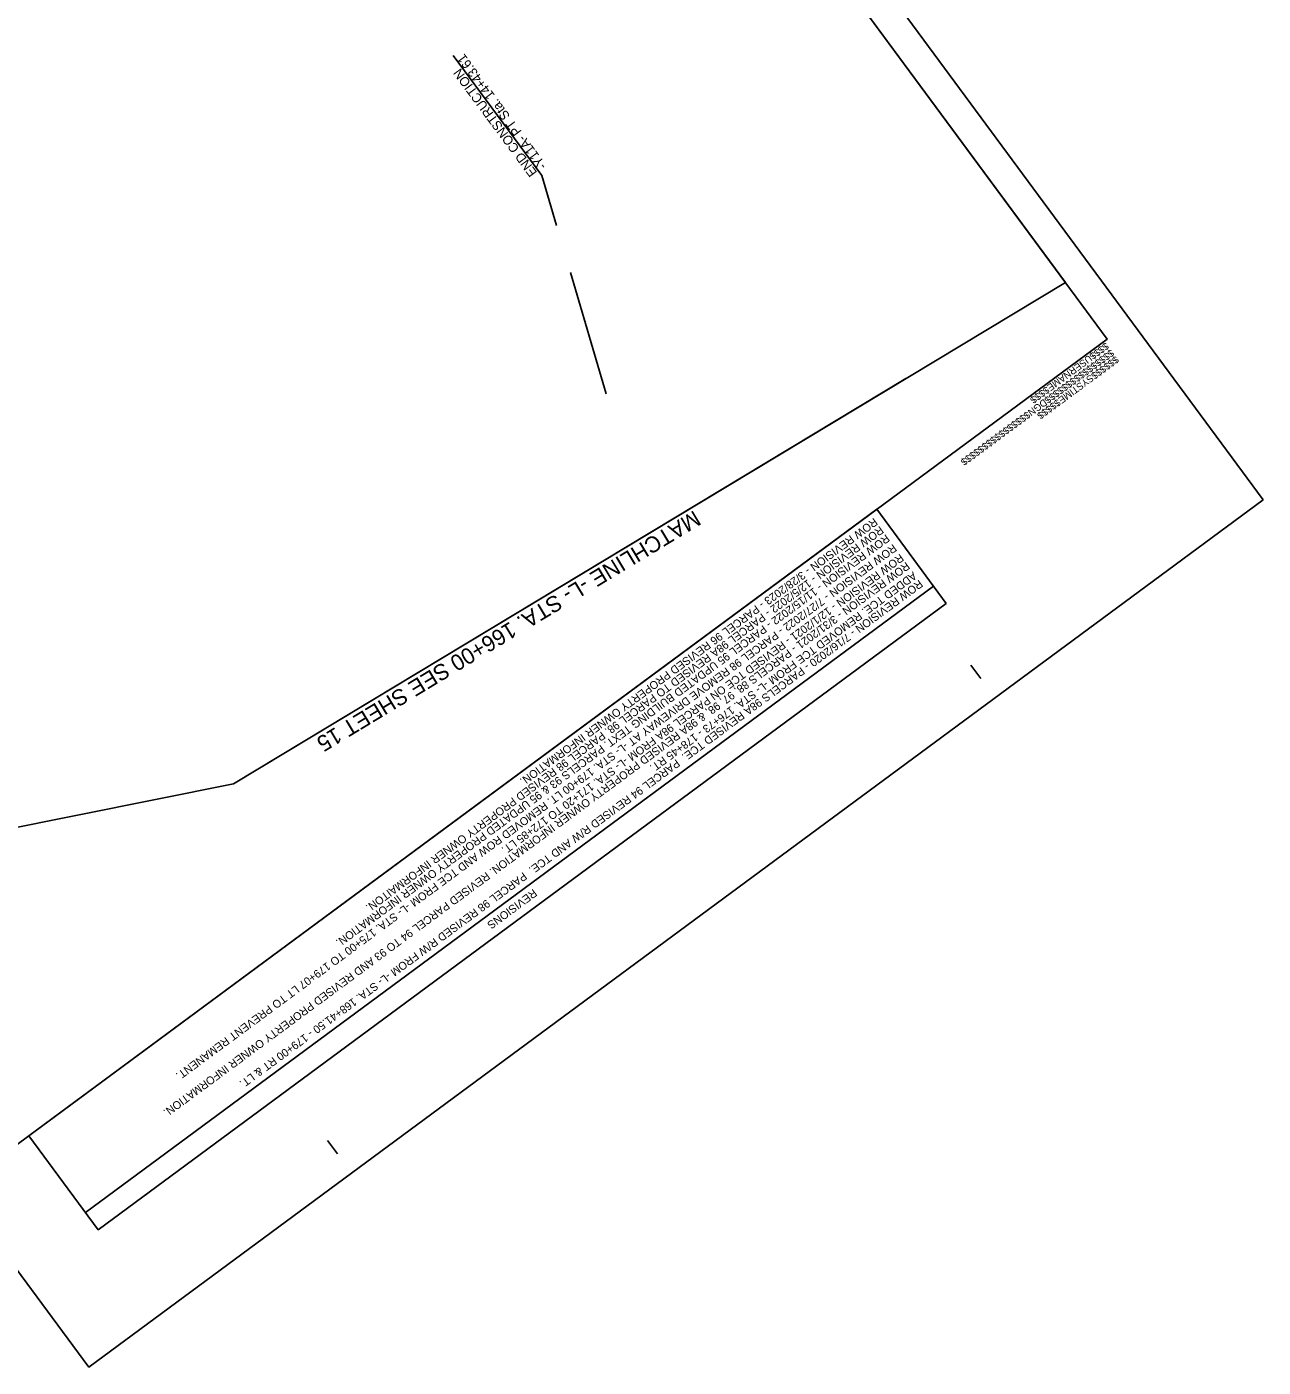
# Model space of a CAD drawing. Extents: x 474314 to 476195, y 501901 to 503905.
# Drawn here: x 475267 to 476195, y 501901 to 502906 of the extents above; entities that cross this region are included whole.
import ezdxf

# ---------------------------------------------------------------- set-up
doc = ezdxf.new("R2010")
doc.units = 0
for name, color, linetype in [('Matchline', 7, 'Continuous'), ('Matchline Text', 7, 'Continuous'), ('Prop Horizontal Alignment Station Label', 7, 'Continuous'), ('Sheet Block Revision CELL', 7, 'Continuous'), ('Sheet Clip Boundary CELL', 7, 'Continuous'), ('Sheet Plan CELL', 7, 'Continuous'), ('Sheet Plot Border Outside CELL', 7, 'Continuous')]:
    doc.layers.add(name, color=color, linetype=linetype)

msp = doc.modelspace()

# ---------------------------------------------------------------- linework, layer by layer
at = {"layer": 'Matchline'}
msp.add_line((475926.7, 502641.9), (475422.2, 502338), dxfattribs=at)
at = {"layer": 'Prop Horizontal Alignment Station Label'}
for p, q in [((475587, 502884.3), (475653.5, 502794.3)), ((475664.6, 502756.7), (475653.5, 502794.3)), ((475701.9, 502630.6), (475675, 502721.6))]:
    msp.add_line(p, q, dxfattribs=at)
at = {"layer": 'Sheet Block Revision CELL'}
msp.add_line((475947.4, 502486.2), (475311.4, 502016.5), dxfattribs=at)
msp.add_lwpolyline([(475956.9, 502473.4), (475320.9, 502003.7), (475268.8, 502074.2), (475904.8, 502543.9)], close=True, dxfattribs=at)
at = {"layer": 'Sheet Clip Boundary CELL'}
msp.add_lwpolyline([(474600.4, 503196.7), (474460.8, 503093.6), (475070.9, 502267.6), (475070.9, 502267.6), (475070.9, 502267.6), (475070.9, 502267.6), (475070.9, 502267.6), (475070.9, 502267.6), (475422.2, 502338), (475422.2, 502338), (476046.5, 502714), (475412.1, 503573), (475380.3, 503549.5), (475256.1, 503717.6), (475223.6, 503693.5), (475026.2, 503617.6), (474540, 503278.5)], close=True, dxfattribs=at)
at = {"layer": 'Sheet Plan CELL'}
for p, q in [((476077.7, 502671.6), (476077.7, 502671.6)), ((475982.9, 502417.1), (475975.5, 502427.1)), ((475500.3, 502060.6), (475492.9, 502070.7))]:
    msp.add_line(p, q, dxfattribs=at)
msp.add_lwpolyline([(474342, 503254.5), (475233.1, 502047.9), (476077.7, 502671.6), (475186.6, 503878.3)], close=True, dxfattribs=at)
at = {"layer": 'Sheet Plot Border Outside CELL'}
msp.add_lwpolyline([(476194.7, 502551.1), (475194.6, 503905.3), (474313.8, 503254.8), (475313.9, 501900.6)], close=True, dxfattribs=at)

# ---------------------------------------------------------------- texts
at = {"layer": 'Matchline Text'}
msp.add_text('MATCHLINE -L- STA. 166+00 SEE SHEET 15', height=12, rotation=211.1357, dxfattribs=at).set_placement((475767.9, 502543.5))
at = {"layer": 'Prop Horizontal Alignment Station Label'}
for s, p in [('-Y11A- PT Sta. 14+43.61', (475657.6, 502801.7)), ('END CONSTRUCTION', (475650.4, 502796.5))]:
    msp.add_text(s, height=7, rotation=126.4463, dxfattribs=at).set_placement(p)
at = {"layer": 'Sheet Block Revision CELL'}
for s, p in [('ROW REVISION - 3/28/2023 - PARCEL 96 REVISED PROPERTY OWNER INFORMATION. ', (475902.7, 502537.8)), ('ROW REVISION - 12/5/2022 - PARCEL 98A REVISED TO PARCEL 98. PARCEL 98 REVISED PROPERTY OWNER INFORMAITON. ', (475907.2, 502531.7)), ('ROW REVISION - 7/27/2022 - PARCEL 98 REMOVE DRIVEWAY AT -L- STA. 179+00 LT. REMOVED ROW AND TCE FROM -L- STA. 175+00 TO 179+07 LT TO PREVENT REMANENT. ', (475917, 502518.2)), ('ROW REVISION - 11/15/2022 - PARCEL 95 UPDATED BUILDING TEXT. PARCELS 93 & 95 UPDATED PROPERTY OWNER INFORMATION. ', (475911.7, 502525.5)), ('ROW REVISION - 12/1/2021 - REVISED TCE ON PARCEL 98A FROM -L- STA. 171+20 TO 172+85 LT. ', (475922.3, 502510.9)), ('ROW REVISION - 3/31/2021 - PARCELS 88, 97, 98, & 98A REVISED PROPERTY OWNER INFORMATION. REVISED PARCEL 94 TO 93 AND REVISED PROPERTY OWNER INFORMATION.', (475926.8, 502504.8)), ('ADDED TCE. REMOVED TCE FROM -L- STA. 176+73 - 178+45 RT.', (475932, 502497.5)), ('ROW REVISION - 7/16/2020 - PARCELS 98A REVISED TCE.  PARCEL 94 REVISED R/W AND TCE.  PARCEL 98 REVISED R/W FROM -L- STA. 168+41.50 - 179+00 RT & LT. ', (475936.6, 502491.4)), ('REVISIONS', (475647.2, 502259.5))]:
    msp.add_text(s, height=6, rotation=216.4463, dxfattribs=at).set_placement(p)
at = {"layer": 'Sheet Plan CELL'}
for s, p in [('$$$$USERNAME$$$$', (476076.5, 502669.3)), ('$$$$$$$$$$$$$$$$DGN$$$$$$$$$$$$$$$$', (476080.4, 502664.1)), ('$$$$$$SYSTIME$$$$$', (476084, 502659.2))]:
    msp.add_text(s, height=5.25, rotation=216.4463, dxfattribs=at).set_placement(p)

doc.saveas('drawing.dxf')
